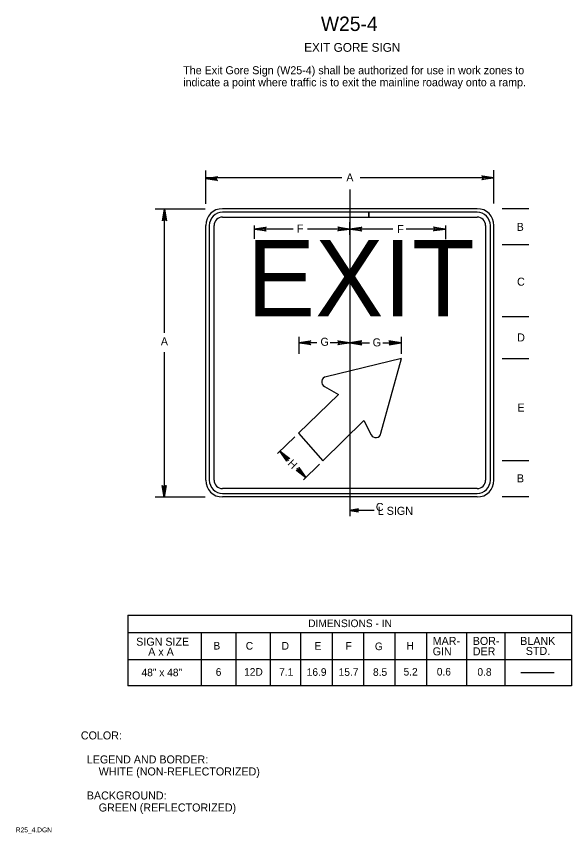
# Model space of a CAD drawing. Extents: x 0.013 to 0.186, y 0.004 to 0.259.
import ezdxf

# ---------------------------------------------------------------- set-up
doc = ezdxf.new("R2010")
doc.units = 0
for name, color, linetype in [('1', 7, 'Continuous'), ('2', 7, 'Continuous'), ('3', 7, 'Continuous')]:
    doc.layers.add(name, color=color, linetype=linetype)

# ---------------------------------------------------------------- blocks, each defined once
blk = doc.blocks.new('RARROW')
at = {"layer": '3'}
for p, q in [((-2.156, 0.28500000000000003), (-2.2665, 0.384625)), ((-2.2665, 0.384625), (0, 0)), ((0, 0), (-2.2665, -0.379125)), ((-2.156, 0.28500000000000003), (-2.075625, 0.12075)), ((0, 0), (-2.156, 0.28500000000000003)), ((-2.14975, -0.2705), (0, 0)), ((-2.075625, 0.12075), (0, 0)), ((0, 0), (-2.074, -0.108)), ((-2.2665, -0.379125), (-2.14975, -0.2705)), ((-2.074, -0.108), (-2.14975, -0.2705))]:
    blk.add_line(p, q, dxfattribs=at)

msp = doc.modelspace()

# ---------------------------------------------------------------- linework, layer by layer
at = {"layer": '1'}
for p, q in [((0.11691375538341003, 0.20504767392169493), (0.11691375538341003, 0.10301292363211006)), ((0.05614192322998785, 0.19903280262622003), (0.071731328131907, 0.19903280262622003)), ((0.05902868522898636, 0.16032609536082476), (0.05902868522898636, 0.19903280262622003)), ((0.15666375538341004, 0.19903280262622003), (0.07716375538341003, 0.19903280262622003)), ((0.1727687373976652, 0.19903280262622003), (0.16442583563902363, 0.19903280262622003)), ((0.12288874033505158, 0.19790780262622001), (0.07716375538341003, 0.19790780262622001)), ((0.12288874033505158, 0.19640780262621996), (0.12288874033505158, 0.19790780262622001)), ((0.15666375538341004, 0.19790780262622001), (0.12288874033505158, 0.19790780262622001)), ((0.12288874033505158, 0.19790780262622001), (0.12288874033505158, 0.19640780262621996)), ((0.07716375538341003, 0.19640780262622), (0.12288874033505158, 0.19640780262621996)), ((0.11691375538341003, 0.19091109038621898), (0.11691375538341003, 0.19482182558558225)), ((0.12288874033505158, 0.19640780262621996), (0.15666375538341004, 0.19640780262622)), ((0.07191375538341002, 0.11428280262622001), (0.07191375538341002, 0.19378280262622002)), ((0.07303875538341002, 0.19378280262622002), (0.07303875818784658, 0.11428280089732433)), ((0.07453875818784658, 0.11428280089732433), (0.07453875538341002, 0.19378280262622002)), ((0.08706375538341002, 0.19380793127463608), (0.08706375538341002, 0.1896364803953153)), ((0.14676375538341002, 0.19380793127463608), (0.14676375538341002, 0.1895206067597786)), ((0.15928875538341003, 0.19378280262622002), (0.15928875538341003, 0.11428280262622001)), ((0.16078875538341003, 0.11428280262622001), (0.16078875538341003, 0.19378280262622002)), ((0.16191375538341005, 0.11428280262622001), (0.16191375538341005, 0.19378280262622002)), ((0.1727687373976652, 0.18778280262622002), (0.16442583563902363, 0.18778280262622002)), ((0.1727687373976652, 0.16528280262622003), (0.16442583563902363, 0.16528280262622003)), ((0.10093875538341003, 0.15904584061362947), (0.10093875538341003, 0.1537156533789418)), ((0.11691375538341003, 0.15904584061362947), (0.11691375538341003, 0.1551351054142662)), ((0.13288875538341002, 0.15904584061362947), (0.13288875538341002, 0.1537156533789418)), ((0.05902868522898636, 0.10903280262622), (0.05902868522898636, 0.15421726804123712)), ((0.1727687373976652, 0.15215780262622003), (0.16442583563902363, 0.15215780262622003)), ((0.1727687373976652, 0.12028280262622), (0.16442583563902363, 0.12028280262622)), ((0.15666375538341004, 0.11165780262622), (0.07716375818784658, 0.11165780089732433)), ((0.07716375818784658, 0.11015780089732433), (0.15666375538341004, 0.11015780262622)), ((0.05614192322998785, 0.10903280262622), (0.071731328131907, 0.10903280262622)), ((0.15666375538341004, 0.10903280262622), (0.07716375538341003, 0.10903280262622)), ((0.1727687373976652, 0.10903280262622), (0.16442583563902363, 0.10903280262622)), ((0.17030116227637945, 0.05423271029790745), (0.18066799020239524, 0.05423271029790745))]:
    msp.add_line(p, q, dxfattribs=at)
for centre, radius, start, end in [((0.07716375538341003, 0.19378280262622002), 0.00525, 90, 180), ((0.15666375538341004, 0.19378280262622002), 0.00525, 0, 90), ((0.07716375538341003, 0.19378280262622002), 0.004125, 90, 180), ((0.15666375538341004, 0.19378280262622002), 0.004125, 0, 90), ((0.07716375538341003, 0.19378280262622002), 0.002625, 90, 180), ((0.15666375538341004, 0.19378280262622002), 0.002625, 0, 90), ((0.07716375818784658, 0.11428280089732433), 0.00525, 180, 270), ((0.07716375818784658, 0.11428280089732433), 0.004125, 180, 270), ((0.07716375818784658, 0.11428280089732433), 0.002625, 180, 270), ((0.15666375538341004, 0.11428280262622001), 0.00525, 270, 0), ((0.15666375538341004, 0.11428280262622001), 0.004125, 270, 0), ((0.15666375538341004, 0.11428280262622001), 0.002625, 270, 0)]:
    msp.add_arc(centre, radius, start, end, dxfattribs=at)
at = {"layer": '3'}
for p, q in [((0.07191375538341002, 0.20055352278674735), (0.07190304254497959, 0.21094935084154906)), ((0.16190668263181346, 0.2006462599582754), (0.161895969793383, 0.2110420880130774)), ((0.114368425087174, 0.20867418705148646), (0.07190968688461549, 0.20867418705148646)), ((0.16189840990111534, 0.20867418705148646), (0.1201041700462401, 0.20867418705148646)), ((0.09917449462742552, 0.1926836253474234), (0.08706375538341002, 0.1926836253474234)), ((0.11691375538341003, 0.1926836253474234), (0.10369356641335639, 0.1926836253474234)), ((0.13034450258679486, 0.1926836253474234), (0.11691375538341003, 0.1926836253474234)), ((0.14676375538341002, 0.1926836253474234), (0.13451595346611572, 0.1926836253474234)), ((0.10660489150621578, 0.15719186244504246), (0.10093875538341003, 0.15719186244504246)), ((0.11691375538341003, 0.15719186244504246), (0.11077634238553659, 0.15719186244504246)), ((0.11691375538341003, 0.15719186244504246), (0.12305116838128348, 0.15719186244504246)), ((0.12722261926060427, 0.15719186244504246), (0.13288875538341, 0.15719186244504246)), ((0.1330041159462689, 0.15221511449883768), (0.10950820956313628, 0.14656877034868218)), ((0.12661635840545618, 0.12890985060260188), (0.1330041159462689, 0.15221511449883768)), ((0.10897181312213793, 0.14349718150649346), (0.11338951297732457, 0.14101333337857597)), ((0.11338951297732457, 0.14101333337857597), (0.10088363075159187, 0.12894766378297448)), ((0.10850232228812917, 0.12034404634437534), (0.12125292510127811, 0.13293016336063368)), ((0.12125292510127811, 0.13293016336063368), (0.12352932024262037, 0.12847101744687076)), ((0.09974673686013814, 0.12784874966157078), (0.09433124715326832, 0.12262388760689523)), ((0.10088363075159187, 0.12894766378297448), (0.10850232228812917, 0.12034404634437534)), ((0.09790542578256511, 0.12045034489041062), (0.09506301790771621, 0.12332989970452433)), ((0.1031882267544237, 0.1150985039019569), (0.10033997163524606, 0.11798398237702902)), ((0.10246461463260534, 0.11438422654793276), (0.10744833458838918, 0.11930365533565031)), ((0.11691375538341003, 0.10486914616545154), (0.12452341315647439, 0.1048770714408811)), ((0.047573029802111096, 0.07217030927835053), (0.047573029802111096, 0.050102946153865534)), ((0.047573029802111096, 0.07217030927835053), (0.1861680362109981, 0.07217030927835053)), ((0.1861680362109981, 0.07217666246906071), (0.1861680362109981, 0.050102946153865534)), ((0.1861680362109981, 0.06660062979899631), (0.047573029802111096, 0.06660062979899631)), ((0.0705002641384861, 0.06660062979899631), (0.0705002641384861, 0.050102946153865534)), ((0.09207579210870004, 0.06660062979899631), (0.09207579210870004, 0.050102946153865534)), ((0.153321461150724, 0.06660062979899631), (0.153321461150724, 0.050102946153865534)), ((0.1653479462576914, 0.06660062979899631), (0.1653479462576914, 0.050102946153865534)), ((0.047668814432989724, 0.05828280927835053), (0.1861680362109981, 0.05828280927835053)), ((0.1861680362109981, 0.050102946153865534), (0.047573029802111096, 0.050102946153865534))]:
    msp.add_line(p, q, dxfattribs=at)
for points in [[(0.08128802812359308, 0.06660062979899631), (0.08128802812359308, 0.050102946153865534)], [(0.10152802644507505, 0.06660062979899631), (0.10152802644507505, 0.050102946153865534)], [(0.11134552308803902, 0.06660062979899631), (0.11134552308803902, 0.050102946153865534)], [(0.12116301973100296, 0.06660062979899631), (0.12116301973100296, 0.050102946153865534)], [(0.13098051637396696, 0.06660062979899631), (0.13098051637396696, 0.050102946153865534)], [(0.1407980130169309, 0.06660062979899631), (0.1407980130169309, 0.050102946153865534)]]:
    msp.add_lwpolyline(points, dxfattribs=at)
for centre, radius, start, end in [((0.10978208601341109, 0.14493831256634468), 0.0016533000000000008, 99.53525307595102, 240.6532207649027), ((0.12499539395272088, 0.12923523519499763), 0.001653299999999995, 207.53160292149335, 348.6495706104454)]:
    msp.add_arc(centre, radius, start, end, dxfattribs=at)

# ---------------------------------------------------------------- block references
for p, xscale, yscale, rotation in [((0.16189840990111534, 0.20867418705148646), 0.0016541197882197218, 0.001636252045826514, -0.08291713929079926), ((0.0718118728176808, 0.20843069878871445), 0.0016541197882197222, 0.001636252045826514, 179.91708286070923), ((0.05902868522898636, 0.19903280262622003), 0.0016541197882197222, 0.001636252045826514, 90.08291713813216), ((0.08706375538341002, 0.1926836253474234), 0.0016541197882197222, 0.001636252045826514, 179.91708286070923), ((0.11691375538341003, 0.1926836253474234), 0.0016541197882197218, 0.001636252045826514, -0.08291713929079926), ((0.11691375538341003, 0.1926836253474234), 0.0016541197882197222, 0.001636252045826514, 179.91708286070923), ((0.14676375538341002, 0.1926836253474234), 0.0016541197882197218, 0.001636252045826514, -0.08291713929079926), ((0.10093875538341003, 0.15719186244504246), 0.0016541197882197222, 0.001636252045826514, 179.91708286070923), ((0.11691375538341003, 0.15719186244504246), 0.0016541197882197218, 0.001636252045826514, -0.08291713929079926), ((0.11691375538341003, 0.15719186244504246), 0.0016541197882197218, -0.001636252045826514, -179.9170828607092), ((0.13288875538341, 0.15719186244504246), 0.0016541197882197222, -0.001636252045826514, 0.08291713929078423), ((0.09506301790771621, 0.12332989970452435), 0.0016541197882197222, 0.001636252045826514, 134.6332094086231), ((0.1031882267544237, 0.1150985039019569), 0.0016541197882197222, 0.001636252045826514, -45.88361105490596), ((0.05898052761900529, 0.10890752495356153), 0.0016541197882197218, 0.001636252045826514, -89.91708286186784), ((0.11676130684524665, 0.10481382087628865), 0.0012409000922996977, -0.0012397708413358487, -179.91625369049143)]:
    msp.add_blockref('RARROW', p, dxfattribs=dict(at, xscale=xscale, yscale=yscale, rotation=rotation))

# ---------------------------------------------------------------- texts
at = {"layer": '1'}
for s, height, p in [('W25-4', 0.0045000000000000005, (0.10787231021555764, 0.2545)), ('EXIT GORE SIGN', 0.00275025, (0.10265053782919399, 0.248)), ('EXIT', 0.023925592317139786, (0.08473814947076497, 0.16537517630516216)), ('48" x 48"', 0.00237527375, (0.05187530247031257, 0.0530666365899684)), ('6', 0.00237527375, (0.07503707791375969, 0.05322113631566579)), ('12D', 0.00237527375, (0.08389912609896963, 0.05323617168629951)), ('7.1', 0.00237527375, (0.09485628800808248, 0.053206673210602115)), ('16.9', 0.00237527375, (0.10344451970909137, 0.053206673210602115)), ('15.7', 0.00237527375, (0.11342546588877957, 0.053206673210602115)), ('8.5', 0.00237527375, (0.12414061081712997, 0.053192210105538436)), ('5.2', 0.00237527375, (0.13369022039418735, 0.05328771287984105)), ('0.6', 0.00237527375, (0.1440657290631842, 0.05330217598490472)), ('0.8', 0.00237527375, (0.15674815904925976, 0.05322113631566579)), ('COLOR:', 0.0024997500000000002, (0.032933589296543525, 0.0333561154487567)), ('  LEGEND AND BORDER:', 0.0024997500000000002, (0.032933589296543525, 0.025856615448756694)), ('      WHITE (NON-REFLECTORIZED)', 0.0024997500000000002, (0.032933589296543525, 0.022106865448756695)), ('  BACKGROUND:', 0.0024997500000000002, (0.032933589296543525, 0.014607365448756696)), ('      GREEN (REFLECTORIZED)', 0.0024997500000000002, (0.032933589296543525, 0.010857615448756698)), ('R25_4.DGN', 0.0015, (0.012625, 0.004375))]:
    msp.add_text(s, height=height, dxfattribs=at).set_placement(p)
at = {"layer": '2'}
for s, p in [('The Exit Gore Sign (W25-4) shall be authorized for use in work zones to', (0.06488900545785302, 0.2409966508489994)), ('indicate a point where traffic is to exit the mainline roadway onto a ramp.', (0.06488900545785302, 0.23724690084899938))]:
    msp.add_text(s, height=0.0024997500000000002, dxfattribs=at).set_placement(p)
at = {"layer": '3'}
for s, height, rotation, p in [('A', 0.0024991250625, 0.08291666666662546, (0.11581387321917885, 0.20751746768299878)), ('F', 0.0024991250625, 359.9170833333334, (0.10037458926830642, 0.19156133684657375)), ('F', 0.0024991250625, 0.08291666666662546, (0.13170598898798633, 0.19143920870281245)), ('B', 0.0024991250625, 359.9170833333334, (0.16899671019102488, 0.1921044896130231)), ('C', 0.0024991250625, 359.9170833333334, (0.16911637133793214, 0.17500130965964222)), ('A', 0.0024991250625, 359.9170833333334, (0.057902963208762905, 0.15636049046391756)), ('G', 0.0024991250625, 359.9170833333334, (0.10774966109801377, 0.1562384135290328)), ('G', 0.0024991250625, 0.08291666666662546, (0.12403898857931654, 0.15603617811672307)), ('D', 0.0024991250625, 0.08291666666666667, (0.16915625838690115, 0.15758199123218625)), ('E', 0.0024991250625, 359.9170833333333, (0.16923241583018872, 0.13568870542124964)), ('H', 0.0024991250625, 315.8898461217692, (0.0972961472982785, 0.11923401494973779)), ('B', 0.0024991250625, 0.08291666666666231, (0.169076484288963, 0.11360568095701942)), ('C', 0.0024991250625, 0.08291666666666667, (0.12503920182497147, 0.10467096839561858)), ('L SIGN', 0.0025238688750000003, 359.91625555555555, (0.12558427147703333, 0.10346116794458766)), ('DIMENSIONS - IN', 0.00237527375, 360, (0.10391269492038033, 0.06841323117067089))]:
    msp.add_text(s, height=height, rotation=rotation, dxfattribs=at).set_placement(p)
for s, height, p in [('SIGN SIZE', 0.0024997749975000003, (0.05021118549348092, 0.06261358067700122)), ('B', 0.0023752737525, (0.07432611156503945, 0.061416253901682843)), ('C', 0.0023752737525, (0.08443056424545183, 0.06138732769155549)), ('H', 0.0023752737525, (0.13462843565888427, 0.061416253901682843)), ('MAR-', 0.0024997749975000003, (0.14277334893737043, 0.06284912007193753)), ('BOR-', 0.0024997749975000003, (0.15529104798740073, 0.06284912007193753)), ('BLANK', 0.0024997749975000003, (0.17009802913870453, 0.06284912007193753)), ('A x A', 0.0024997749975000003, (0.053961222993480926, 0.05948854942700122)), ('D', 0.0023752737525, (0.09562489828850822, 0.06138732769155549)), ('E', 0.0023752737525, (0.10588740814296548, 0.06135840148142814)), ('F', 0.0023752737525, (0.11557243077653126, 0.06138732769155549)), ('G', 0.0023752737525, (0.1247369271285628, 0.0612282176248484)), ('GIN', 0.0024997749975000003, (0.14277334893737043, 0.05959908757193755)), ('DER', 0.0024997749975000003, (0.15529104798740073, 0.05959908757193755)), ('STD.', 0.0024997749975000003, (0.17184804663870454, 0.059724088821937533))]:
    msp.add_text(s, height=height, dxfattribs=at).set_placement(p)

doc.saveas('drawing.dxf')
